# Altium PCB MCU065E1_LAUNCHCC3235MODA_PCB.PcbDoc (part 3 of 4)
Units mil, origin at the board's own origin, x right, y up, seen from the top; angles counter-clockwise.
Board outline 2300 x 4280 mil, 4 copper layers (TOP, GND, PWR, BOTTOM), stack 62 mil thick; 300 components, 199 nets, 970 pads, 475 vias.
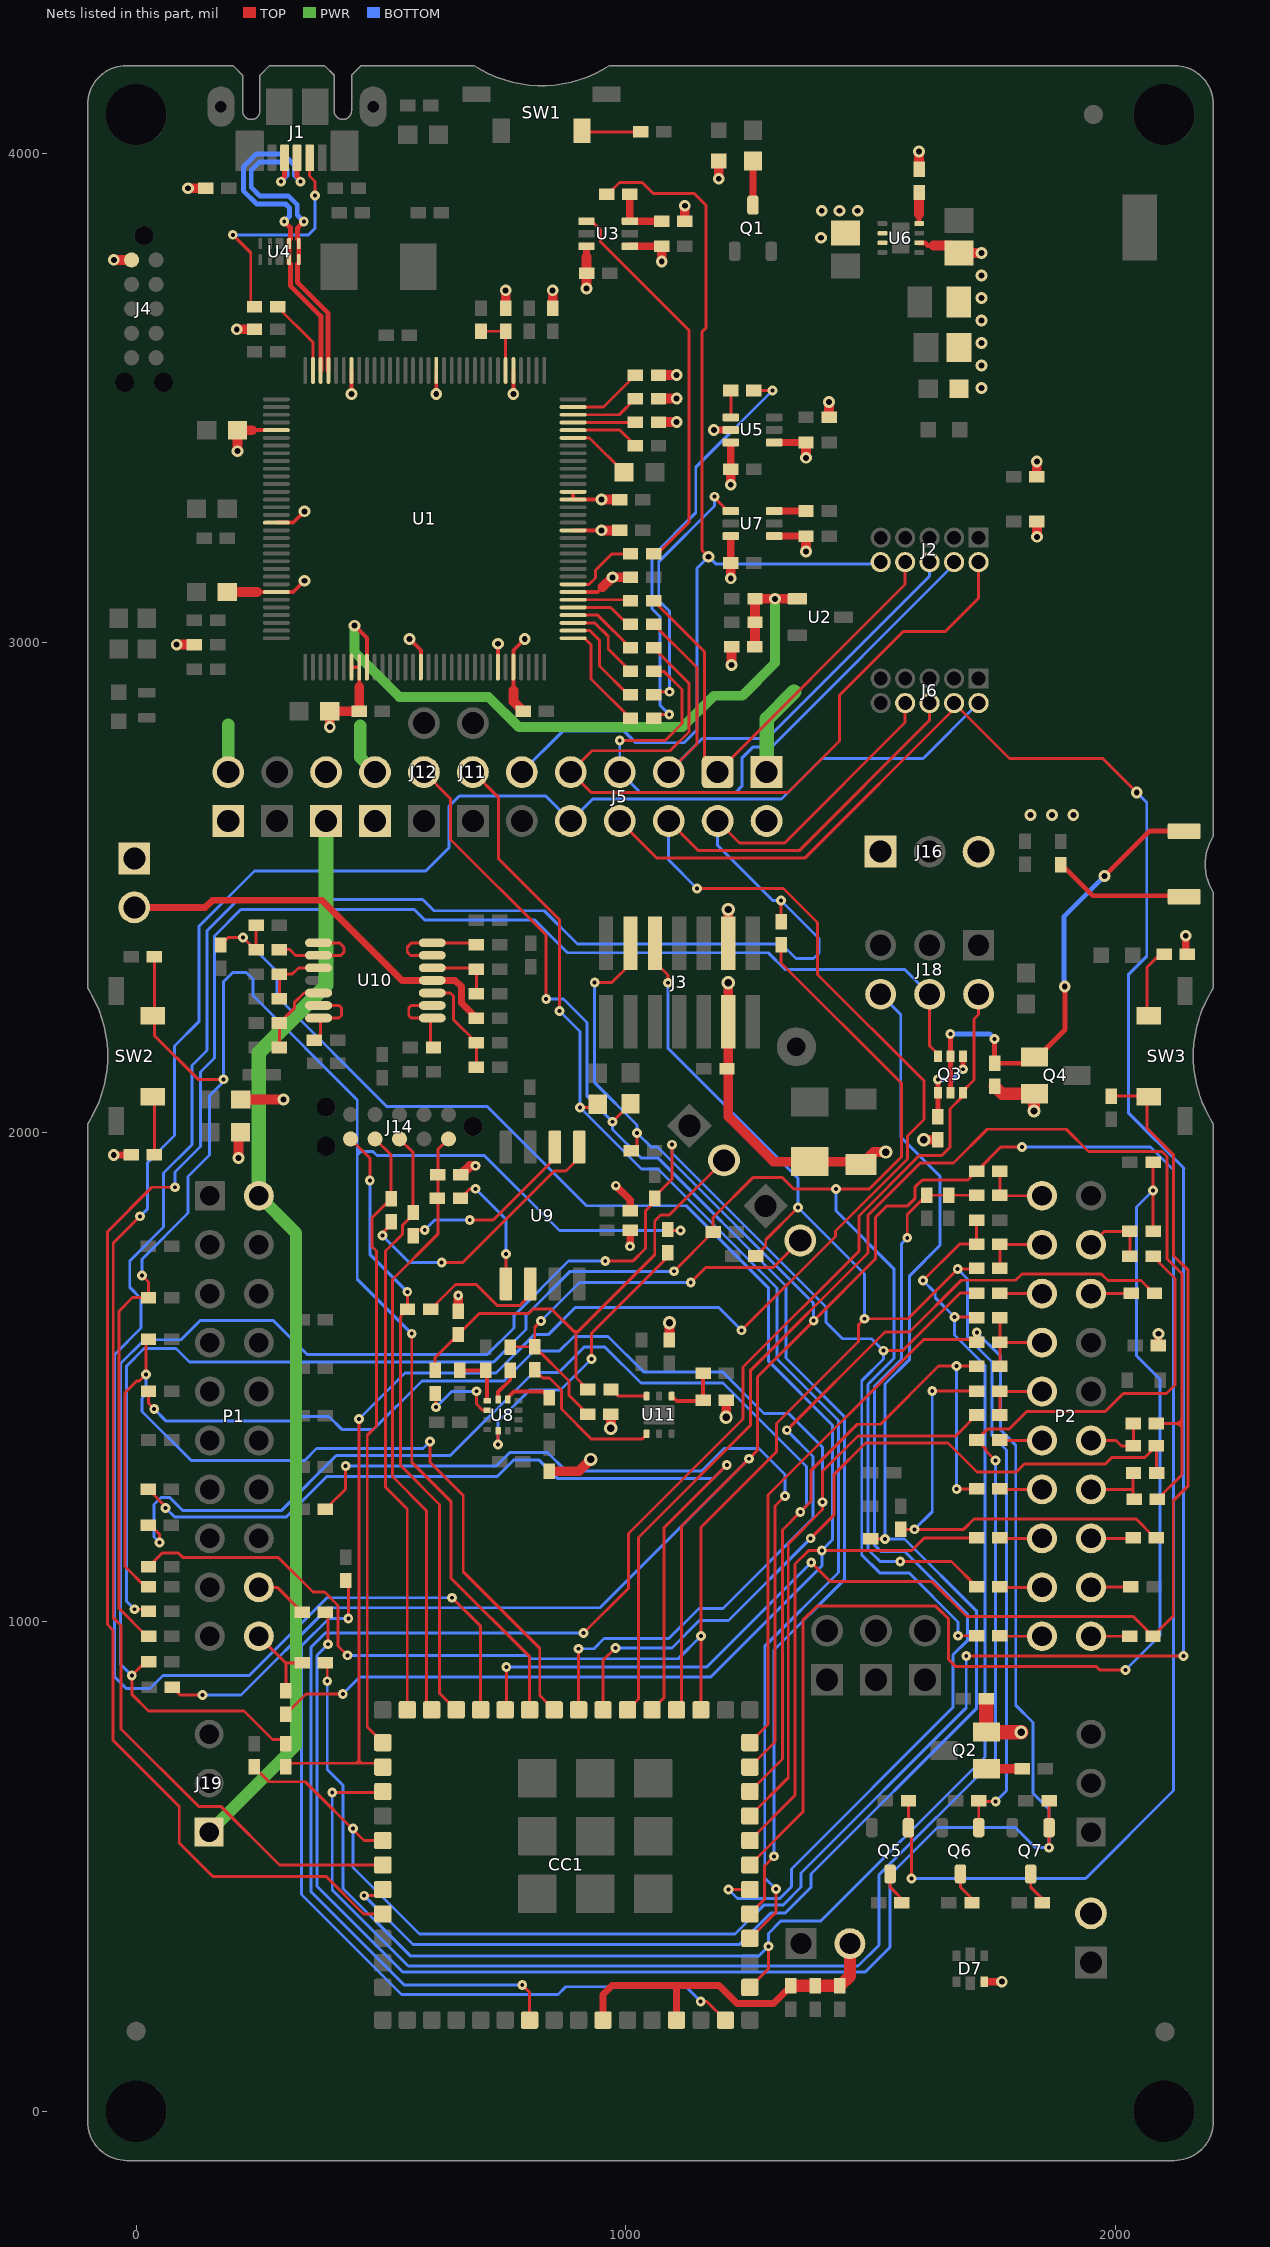
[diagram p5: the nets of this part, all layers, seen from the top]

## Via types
v1: diameter 20, hole 8, TOP to BOTTOM, tented both sides, 270 vias
v2: diameter 24, hole 12, TOP to BOTTOM, tented both sides, 142 vias
v3: diameter 19.68, hole 7.87, TOP to BOTTOM, 36 vias
v4: diameter 27, hole 15, TOP to BOTTOM, tented both sides, 23 vias
v5: diameter 19.68, hole 7.87, TOP to BOTTOM, tented bottom, 4 vias

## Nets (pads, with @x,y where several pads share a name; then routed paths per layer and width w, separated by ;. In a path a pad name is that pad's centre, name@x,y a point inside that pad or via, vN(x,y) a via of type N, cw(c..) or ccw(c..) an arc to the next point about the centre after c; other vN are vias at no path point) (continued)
NetP1_29: P1.29 R87.1 | length 109.9
  TOP w6: P1.29@250.7,1070.26 288.12,1070.26 R87.1@339.38,1019
NetP1_30: P1.30 R91.1 R94.1 | length 169
  TOP w6: P1.30@250.7,970.26 304.96,916 ; R94.1@306,858.62 306,914.96 304.96,916 ; R91.1@339.38,916 304.96,916
NetP2_11: P2.11 R93.1 | length 79.5
  TOP w6: P2.11@1950.7,970.26 R93.1@2030.16,970.26
NetP2_12: P2.12 R89.1 | length 81.9
  TOP w6: P2.12@1950.7,1070.26 1951.7,1071.27 R89.1@2032.16,1071.27
NetP2_13: P2.13 R85.1 | length 86.9
  TOP w6: P2.13@1950.7,1170.26 2036.16,1170.26 R85.1@2037.16,1171.27
NetP2_14: P2.14 R81.1 R99.1 | length 140.7
  TOP w6: P2.14@1950.7,1270.26 2036.16,1270.26 ; R99.1@2037.58,1303.88 2036.16,1302.46 2036.16,1270.26 ; R81.1@2039.18,1250.48 2036.16,1253.5 2036.16,1270.26
NetP2_15: P2.15 R77.1 R96.1 | length 137
  TOP w6: P2.15@1950.7,1370.26 2001.82,1370.26 2013,1359.09 R77.1@2037.16,1359.09 R96.1@2037.16,1404.97
NetP2_18: P2.18 R67.1 | length 83
  TOP w6: P2.18@1950.7,1670.26 2032.24,1670.26 R67.1@2033.24,1671.27
NetP2_19: P2.19 R59.1 R63.1 | length 142
  TOP w6: P2.19@1950.7,1770.26 1977.85,1797.42 R59.1@2030.31,1797.42 R63.1@2030.27,1746.34
NetP2_31: P2.31 R92.2 | length 86.7
  TOP w6: R92.2@1764.41,971.27 1765.41,970.26 P2.31@1850.7,970.26
NetP2_32: P2.32 R88.2 | length 86.7
  TOP w6: R88.2@1764.41,1071.27 1765.41,1070.26 P2.32@1850.7,1070.26
NetP2_33: P2.33 R84.2 | length 86.7
  TOP w6: R84.2@1764.41,1171.27 1765.41,1170.26 P2.33@1850.7,1170.26
NetP2_34: P2.34 R80.2 | length 86.7
  TOP w6: R80.2@1764.41,1271.27 1765.41,1270.26 P2.34@1850.7,1270.26
NetP2_35: P2.35 R76.2 | length 86.7
  TOP w6: R76.2@1764.41,1371.27 1765.41,1370.26 P2.35@1850.7,1370.26
NetP2_36: P2.36 R73.2 R101.2 | length 135.7
  TOP w6: R101.2@1764.41,1422.27 R73.2@1764.41,1471.27 1765.41,1470.26 P2.36@1850.7,1470.26
NetP2_37: P2.37 R70.2 R95.2 R98.2 | length 185.7
  TOP w6: R98.2@1764.41,1522.27 R70.2@1764.41,1571.27 ; R95.2@1764.41,1621.27 R70.2@1764.41,1571.27 ; P2.37@1850.7,1570.26 1765.41,1570.26 R70.2@1764.41,1571.27
NetP2_38: P2.38 R66.2 | length 86.7
  TOP w6: R66.2@1764.41,1671.27 1765.41,1670.26 P2.38@1850.7,1670.26
NetP2_39: P2.39 R54.2 R62.2 | length 135.7
  TOP w6: R62.2@1764.41,1722.27 R54.2@1764.41,1771.27 1765.41,1770.26 P2.39@1850.7,1770.26
NetP2_40: P2.40 R53.2 R60.2 | length 135.7
  TOP w6: R60.2@1764.41,1920.27 R53.2@1764.41,1871.27 1765.41,1870.26 P2.40@1850.7,1870.26
NetQ1_3: Q1.3 R30.1 | length 90
  TOP w15: Q1.3@1260.14,3894.26 R30.1@1260.14,3984.26
NetQ2_1: Q2.1 R105.1 | length 73.4
  TOP w20: Q2.1@1736.83,699.71 R105.1@1810.21,699.71
NetQ3_1: Q3.1 Q3.4 R143.1 | length 162.4
  TOP w10: R143.1@1637.78,2031.92 Q3.1@1637.78,2080.72 v1(1637.78,2107.53) ; v1(1688.97,2128.71) Q3.4@1688.97,2155.52
  BOTTOM w10: v1(1637.78,2107.53) 1667.78,2107.53 v1(1688.97,2128.71)
NetQ3_2: Q3.2 Q3.5 Q4.1 R144.1 SW4.2 | length 988.6
  TOP w10: Q3.2@1663.37,2080.72 Q3.5@1663.37,2155.52 v1(1663.37,2201) ; v1(1753.78,2190.74) R144.1@1753.78,2140.89 1822.69,2140.89 Q4.1@1835.31,2153.5 1841.5,2153.5 1897.58,2209.58 v2@1897.58,2297.5 ; v2(1978.23,2523.25) 2070.57,2615.59 SW4.2@2110.5,2615.59 ; SW4.2@2110.5,2615.61 2116.65,2621.76 SW4.2@2141,2621.76
  BOTTOM w10: v1(1663.37,2201) 1743.52,2201 v1(1753.78,2190.74) ; v2@1895.45,2297.5 1895.45,2440.47 v2(1978.23,2523.25)
  other v2: 1897.22,2297.5
NetQ5_3: Q5.3 R145.1 | length 71.6
  TOP w6: Q5.3@1540.43,484.73 1540.43,457.72 R145.1@1571.93,426.22
NetQ6_3: Q6.3 R146.1 | length 71.6
  TOP w6: Q6.3@1684.05,484.73 1684.05,457.72 R146.1@1715.55,426.22
NetQ7_3: Q7.3 R147.1 | length 71.6
  TOP w6: Q7.3@1827.68,484.73 1827.68,457.72 R147.1@1859.17,426.22
NetR2_2: R2.2 U1.33 | length 225.8
  TOP w6: U1.33@892.71,3009.15 916.17,3009.15 929.43,2995.89 929.43,2926.16 R2.2@1009.95,2845.64
NetR3_1: R3.1 U1.95 | length 159.7
  TOP w6: R3.1@289.02,3686.18 361.21,3613.99 U1.95@361.21,3556.4
NetR4_2: R4.2 U1.34 | length 197.8
  TOP w6: U1.34@892.71,3024.9 926.83,3024.9 946.38,3005.35 946.38,2952.44 R4.2@1005.18,2893.64
NetR6_2: R6.2 U1.35 | length 173.6
  TOP w6: U1.35@892.71,3040.65 937.12,3040.65 964.52,3013.25 964.52,2987.07 R6.2@1009.95,2941.64
NetR7_2: R7.2 U1.36 | length 144.9
  TOP w6: U1.36@892.71,3056.4 943.19,3056.4 R7.2@1009.95,2989.64
NetR8_2: R8.2 U1.37 | length 131.5
  TOP w6: U1.37@892.71,3072.15 969.51,3072.15 1004.01,3037.64 R8.2@1009.95,3037.64
NetR9_2: R9.2 U1.38 | length 118.2
  TOP w6: U1.38@892.71,3087.89 1007.7,3087.89 R9.2@1009.95,3085.64
NetR10_2: R10.2 U1.40 | length 152.1
  TOP w6: U1.40@892.71,3119.39 925.26,3119.39 938.31,3132.44 938.31,3147.98 971.97,3181.64 R10.2@1009.95,3181.64
NetR16_1: R16.1 U1.63 | length 154.3
  TOP w6: U1.63@892.71,3481.59 954.65,3481.59 R16.1@1019.95,3546.89
NetR17_1: R17.1 U1.62 | length 140.9
  TOP w6: U1.62@892.71,3465.85 986.9,3465.85 R17.1@1019.95,3498.89
NetR18_1: R18.1 U1.61 | length 127.6
  TOP w6: U1.61@892.71,3450.1 1019.16,3450.1 R18.1@1019.95,3450.89
NetR20_1: R20.1 U1.60 | length 140.3
  TOP w6: U1.60@892.71,3434.35 988.49,3434.35 R20.1@1019.95,3402.89
NetR24_1: R24.1 R25.2 U1.70 | length 130.4
  TOP w6: R25.2@704.56,3636.4 R24.1@754.91,3636.4 U1.70@754.91,3556.4
NetR27_2: R27.2 U1.59 | length 133.2
  TOP w6: U1.59@892.71,3418.6 926.46,3418.6 R27.2@996.81,3348.25
NetR28_1: R28.1 R29.2 U3.3 | length 120
  TOP w15: R29.2@1008.76,3916.37 U3.3@1008.76,3861.37 R28.1@1073.76,3861.37
NetR32_2: R32.2 SW1.1 | length 120
  TOP w6: SW1.1@910.98,4043.62 R32.2@1030.98,4043.62
NetR34_1: R34.1 U5.4 | length 55
  TOP w6: U5.4@1214.86,3460.37 R34.1@1214.86,3515.37
NetR36_1: R36.1 U6.8 | length 63.4
  TOP w10: U6.8@1599.51,3856.45 1599.51,3875.64
  TOP w20: 1599.51,3875.64 R36.1@1599.51,3919.88
NetR37_2: R37.2 U7.3 | length 65
  TOP w15: U7.3@1303.45,3269.19 R37.2@1368.45,3269.19
NetR40_2: R40.2 U9.1 | length 258.7
  TOP w6: R40.2@662.65,1865.18 681.85,1884.38 v1(693.3,1884.38) ; U9.1@755.4,1690.11 v1(755.6,1751.48)
  BOTTOM w6: v1(693.3,1884.38) 755.6,1822.08 v1(755.6,1751.48)
NetR41_2: R41.2 U9.6 | length 377.8
  TOP w6: R41.2@565.94,1788.8 577.3,1800.16 v1(589.59,1800.16) ; v1(681.5,1820.68) 729.45,1820.68 855.4,1946.62 U9.6@855.4,1969.64
  BOTTOM w6: v1(589.59,1800.16) 610.11,1820.68 v1(681.5,1820.68)
NetR42_2: R42.2 U9.5 | length 571.2
  TOP w6: v1(503,1788.78) 503,1793.48 521.02,1811.5 R42.2@521.02,1817.18 ; v1(624.2,1733.88) 667.41,1733.88 854.39,1920.86 878.04,1920.86 905.4,1948.23 U9.5@905.4,1969.64
  BOTTOM w6: v1(503,1788.78) 557.9,1733.88 v1(624.2,1733.88)
NetR43_2: R43.2 U9.2 | length 274
  TOP w6: R43.2@601.62,1638 652.38,1688.76 694.86,1688.76 737.98,1645.65 782.97,1645.65 805.4,1668.08 U9.2@805.4,1690.11
NetR108_2: R108.2 R112.2 U10.10 | length 135.5
  TOP w6: R112.2@292.48,2273.14 R108.2@292.48,2323.14 318.86,2323.14 331.45,2335.73 U10.10@372.72,2335.73
NetR109_1: R109.1 U10.8 U10.9 | length 201
  TOP w6: R109.1@292.48,2373.14 313.86,2373.14 325.68,2361.32 U10.9@372.72,2361.32 418.04,2361.32 424.37,2367.65 424.37,2377.75 415.21,2386.91 U10.8@376.65,2386.91
NetR110_2: R110.2 R113.2 U10.5 | length 141.3
  TOP w6: U10.5@605,2335.73 692.64,2335.73 R110.2@695.24,2333.14 R113.2@695.24,2283.14
NetR111_1: R111.1 U10.6 U10.7 | length 206.6
  TOP w6: U10.6@601.06,2361.32 560.68,2361.32 553.86,2368.14 553.86,2378.14 562.63,2386.91 U10.7@605,2386.91 691.46,2386.91 R111.1@695.24,2383.14
NetR116_2: R116.2 R122.2 U10.12 | length 162.2
  TOP w6: R122.2@292.48,2173.14 R116.2@292.48,2223.14 323.86,2254.52 323.86,2265.61 342.79,2284.55 U10.12@372.72,2284.55
NetR117_1: R117.1 U10.13 U10.14 | length 156.6
  TOP w6: R117.1@364.24,2187.84 376.65,2200.26 376.65,2233.37 414.59,2233.37 419.77,2238.55 419.77,2254.05 414.86,2258.96 U10.13@376.65,2258.96
NetR119_2: R119.2 R123.2 U10.3 | length 210.5
  TOP w6: U10.3@605,2284.55 642.08,2284.55 648.49,2278.14 648.49,2229.89 R119.2@695.24,2183.14 R123.2@695.24,2133.14
NetR120_1: R120.1 U10.1 U10.2 | length 170.7
  TOP w6: U10.2@601.06,2258.96 561.88,2258.96 556.97,2254.05 556.97,2238.65 562.25,2233.37 601.06,2233.37 601.06,2179.56 R120.1@607.48,2173.14
NetR128_1: R128.1 R132.2 U11.4 | length 124.7
  TOP w8: U11.4@1093.98,1460.99 1104.39,1450.58 1156.33,1450.58 R128.1@1158.39,1452.64 R132.2@1158.39,1507.79
NetR129_1: R129.1 R131.1 U8.1 | length 112.3
  TOP w8: R129.1@665.04,1513.56 R131.1@714.29,1513.56 714.29,1508.29 717.2,1505.37 U8.1@717.2,1451.71
NetR133_2: R133.2 U8.5 | length 599.8
  TOP w6: v1(739.44,1362.34) U8.5@739.44,1390.1 ; v1(930.3,1536.98) 930.3,1589.48 1085.9,1745.08 R133.2@1085.9,1754.05
  BOTTOM w6: v1(739.44,1362.34) 739.44,1408.92 804.1,1473.58 866.9,1473.58 v1(930.3,1536.98)
NetR135_1: R135.1 U11.6 | length 78.2
  TOP w6: R135.1@970.17,1474.4 983.58,1460.99 U11.6@1042.8,1460.99
NetR136_1: R136.1 U11.1 | length 315.7
  TOP w6: R136.1@814.29,1514.56 830.79,1498.06 844.32,1498.06 868.77,1473.61 868.77,1434.69 930.52,1372.94 1033.39,1372.94 1042.8,1382.35 U11.1@1042.8,1384.22
NetR138_1: R138.1 U8.2 | length 178.2
  TOP w6: R138.1@610.62,1466.32 612.72,1464.21 v1(612.72,1438.33) ; v1(695.2,1470.78) 695.2,1444.57 707.75,1432.03 U8.2@717.2,1432.03
  BOTTOM w6: v1(612.72,1438.33) 645.17,1470.78 v1(695.2,1470.78)
NetR140_1: R140.1 U8.11 | length 99.5
  TOP w8: U8.11@759.13,1454.27 759.13,1458.15 771.56,1470.58 831.52,1470.58 R140.1@844.29,1457.81
NetR141_1: R141.1 U8.12 | length 69.6
  TOP w8: U8.12@739.44,1454.27 739.44,1469.34 764.29,1494.19 R141.1@764.29,1513.56
NetR148_1: R148.1 SW2.2 | length 120
  TOP w6: R148.1@37.16,1953.6 SW2.2@37.16,2073.6
NetR149_1: R149.1 SW3.2 | length 144.1
  TOP w6: SW3.2@2065.14,2238.95 2065.14,2336.98 2092.19,2364.02 R149.1@2100.04,2364.02
NetR154_2: R154.2 SW4.1 | length 248.9
  TOP w10: R154.2@1888.8,2548.72 1954.46,2483.06 SW4.1@2110.5,2483.06
P01_GPIO_10: CC1.3 J3.9 Q6.1 R62.1 R86.1 R130.1 R151.2 | length 4809.4
  TOP w6: R86.1@25.16,1112.26 52.9,1140 86.79,1140 96.04,1130.75 291.1,1130.75 361.04,1060.81 385.1,1060.81 412.57,1033.34 412.57,950.38 v1(431.67,931.28) ; J3.9@1059.79,2380.75 1059.79,2348.15 1086.6,2321.34 v1(1086.6,2305.36) ; CC1.3@1153.9,819.92 v1(1153.9,970.88) 1153.9,1192.88 1308.3,1347.27 1308.3,1405.21 1475.51,1572.42 1475.51,1606.65 v1(1487.78,1618.92) 1576.81,1618.92 v1(1678.36,1720.47) 1715.37,1720.47 R62.1@1717.16,1722.27 ; R130.1@1265.72,1747.18 1286.26,1767.71 1286.26,1780.26 v1(1351.98,1845.98) ; Q6.1@1721.45,579.22 R151.2@1721.45,634.22 1723.22,632.45 v1(1755.95,632.45)
  BOTTOM w6: v1(431.67,931.28) 799.52,931.28 806.47,924.33 1107.36,924.33 v1(1153.9,970.88) ; v1(1086.6,2305.36) 1086.6,2171.48 1351.98,1906.1 v1(1351.98,1845.98) 1487.78,1710.18 v1(1487.78,1618.92) ; v1(1678.36,1720.47) 1698.45,1700.39 1698.45,1580.94 1748.59,1530.8 1748.59,1380.66 1778.25,1351 1778.25,654.75 v1(1755.95,632.45)
P02_GPIO_11: CC1.4 J3.11 Q5.1 R60.1 R90.1 R137.1 R150.2 | length 6349.6
  TOP w6: R90.1@73.62,866 89.62,850 v1(135.52,850) ; v1(936.8,2305.96) 971.78,2305.96 1009.79,2343.97 J3.11@1009.79,2380.75 ; R137.1@1011.68,1962.08 1023.43,1973.83 v1(1023.43,1998.46) ; CC1.4@1103.9,819.92 1114.36,830.38 1114.36,1195.41 v1(1251.82,1332.87) 1269.33,1350.38 1269.5,1350.38 1269.5,1500.38 v1(1384.2,1615.08) 1510.51,1741.39 1510.51,1826.24 1533.87,1849.6 1576.21,1849.6 1590.88,1864.27 1590.88,1887.43 1606.14,1902.7 1699.59,1902.7 R60.1@1717.16,1920.27 1766.51,1969.62 v1(1809.5,1969.62) ; R150.2@1577.83,634.22 Q5.1@1577.83,579.22 1584.04,573.01 v1(1584.04,475.59)
  BOTTOM w6: v1(135.52,850) 213.98,850 392.52,1028.54 947.49,1028.54 v1(1251.82,1332.87) ; v1(936.8,2305.96) 936.8,2101.28 1023.43,2014.65 v1(1023.43,1998.46) 1052.21,1969.68 1064.84,1969.68 1384.2,1650.31 v1(1384.2,1615.08) ; v1(1584.04,475.59) 1939.82,475.59 2119.17,654.94 2119.17,1922.83 2072.38,1969.62 v1(1809.5,1969.62)
P03_GPIO_12: CC1.9 R68.1 R102.1 | length 1929.6
  TOP w6: R102.1@25.16,1071.26 18.74,1071.26 -22.73,1112.73 -22.73,1467.58 1.76,1492.07 6.8,1492.07 v1(19.9,1505.18) 19.9,1572 R68.1@25.16,1577.26 ; v1(600.39,1367.93) 600.39,1325.81 668.22,1257.98 668.22,1102.05 824.57,945.7 824.57,849.25 CC1.9@853.9,819.92
  BOTTOM w6: v1(19.9,1505.18) 19.9,1463.68 12.1,1455.88 12.1,1429.68 111.98,1329.8 344.74,1329.8 368.71,1353.77 586.24,1353.77 v1(600.39,1367.93)
P04_GPIO_13: CC1.10 R64.1 R103.1 R133.1 R155.2 SW2.1 | length 4397.7
  TOP w6: v1(11.9,1707.17) 25.17,1693.91 R64.1@25.17,1662.26 -7.36,1662.26 -34.73,1634.89 -34.73,1026.98 22.21,970.04 R103.1@23.95,970.04 ; R155.2@37.16,2358.95 37.16,2238.95 37.16,2197.84 126.9,2108.09 v1(178.3,2108.09) ; v1(563.06,1588.41) 563.06,1325.77 643.66,1245.18 643.66,1088.55 803.9,928.31 CC1.10@803.9,819.92 ; R133.1@1085.9,1801.3 1089.02,1798.18 1089.89,1799.04 v1(1111.92,1799.04)
  BOTTOM w6: v1(11.9,1707.17) 11.9,1740.68 106,1834.77 106,1909.63 149.97,1953.6 149.97,2074.65 178.3,2102.98 v1(178.3,2108.09) 178.3,2307.51 197.59,2326.79 224.49,2326.79 238.47,2312.82 238.47,2279.21 451.76,2065.92 451.76,1968.28 ; v1(563.06,1588.41) 451.76,1699.72 451.76,1953.23 ; v1(1111.92,1799.04) 864.7,1799.04 711.36,1952.38 491.84,1952.38 483.46,1960.75 459.28,1960.75 ; 451.76,1953.23 459.28,1960.75 ; 451.76,1953.23 451.76,1960.75 ; 451.76,1960.75 451.76,1968.28 ; 451.76,1960.75 459.28,1960.75 ; 451.76,1968.28 459.28,1960.75
P05_GPIO_14: CC1.5 R78.1 | length 1846.4
  TOP w6: R78.1@25.16,1271.26 25.16,1269.98 60.2,1234.95 v1(60.2,1232.38) ; CC1.5@1053.9,819.92 1078.58,844.6 1078.58,1192.16 v1(1206.8,1320.38)
  BOTTOM w6: v1(60.2,1232.38) 78.78,1213.79 306.75,1213.79 389.96,1297 738.15,1297 771.19,1330.04 823.31,1330.04 860.43,1292.93 1179.35,1292.93 v1(1206.8,1320.38)
P06_GPIO_15: CC1.6 R81.2 R96.2 | length 2729.4
  TOP w6: CC1.6@1003.9,819.92 1026.1,842.12 1026.1,1172.03 1254.68,1400.61 1254.68,1512.88 1494.91,1753.11 1494.91,1830.36 1601.9,1937.35 1669.97,1937.35 1738.74,2006.12 1899.99,2006.12 1945.55,1960.56 2095.59,1960.56 2105.91,1950.23 2105.91,1741.38 2136.4,1710.89 2136.4,1413.3 ; R96.2@2084.41,1404.97 2128.07,1404.97 ; R81.2@2086.42,1250.48 2136.4,1300.45 2136.4,1396.64 ; 2128.07,1404.97 2136.4,1413.3 ; 2128.07,1404.97 2136.4,1404.97 ; 2128.07,1404.97 2136.4,1396.64 ; 2136.4,1396.64 2136.4,1404.97 ; 2136.4,1404.97 2136.4,1413.3
P07_GPIO_16: CC1.7 R77.2 R99.2 | length 1565
  TOP w6: CC1.7@953.9,820.94 953.9,921.21 v1(979.2,946.51) ; v1(1378,1170.38) 1425.32,1217.69 1425.32,1300.47 1489.85,1365 1658.88,1365 1717.98,1305.9 1798.11,1305.9 1814.5,1322.28 1979.98,1322.28 1993.48,1335.78 2061.1,1335.78 R77.2@2084.41,1359.09 2084.41,1304.29 R99.2@2084.82,1303.88
  BOTTOM w6: v1(979.2,946.51) 1094.59,946.51 1150.61,1002.53 1210.15,1002.53 v1(1378,1170.38)
P08_GPIO_17: CC1.8 R67.2 | length 1815
  TOP w6: CC1.8@903.9,820.94 v1(903.9,944.78) ; v1(1329.3,1391.28) 1529.86,1591.84 1580.06,1591.84 1685.87,1697.65 1796.64,1697.65 1809.53,1710.54 1971.91,1710.54 1985.37,1697.08 2052.86,1697.08 2076.99,1672.96 2078.8,1672.96 R67.2@2080.49,1671.27
  BOTTOM w6: v1(903.9,944.78) 935.19,944.78 955.92,965.51 1088.13,965.51 1149.86,1027.23 1198.66,1027.23 1382.93,1211.51 1382.93,1337.65 v1(1329.3,1391.28)
P15_GPIO_22: CC1.11 R93.2 R156.2 SW3.1 | length 2800.4
  TOP w6: CC1.11@753.9,820.94 756.25,823.29 v1(756.25,907.72) ; v1(1379.2,1121.08) 1417.75,1082.53 1625.51,1082.53 1697.28,1010.76 2036.91,1010.76 R93.2@2077.41,970.26 2118.8,1011.65 2118.8,1247.28 2149.31,1277.8 2149.31,1718.02 2118.91,1748.42 2118.91,1954.2 2065.14,2007.97 2065.14,2073.6 R156.2@1992.54,2073.6
  BOTTOM w6: v1(756.25,907.72) 1165.84,907.72 v1(1379.2,1121.08)
P16_GPIO_23: R46.1 R88.1 R97.1 R134.1 | length 3967.5
  TOP w6: v1(-3.51,1025.46) 20.96,1025.46 R97.1@25.16,1021.26 ; v1(1098.55,1716.04) 1178.78,1796.27 1178.78,1825.75 1260.95,1907.92 1319.73,1907.92 1343.59,1884.06 v1(1429.55,1884.06) 1497.7,1884.06 1563.91,1950.27 1563.91,2099.46 1317.6,2345.78 R46.1@1317.6,2382.85 ; v1(1561.03,1122.83) 1665.61,1122.83 R88.1@1717.16,1071.27
  BOTTOM w6: v1(-3.51,1025.46) -19.84,1041.79 -19.84,1522.09 16.3,1558.23 81.47,1558.23 109.26,1530.44 730.37,1530.44 796.66,1596.73 796.66,1625.87 886.67,1715.88 1098.38,1715.88 v1(1098.55,1716.04) ; v1(1429.55,1884.06) 1429.55,1839.6 1547.99,1721.16 1547.99,1537.68 1495.35,1485.04 1495.35,1147.5 1520.03,1122.83 v1(1561.03,1122.83)
P16_JTAG_TDI: CC1.12 J5.2 J6.8 R46.2 | length 4934.7
  TOP w6: v1(645.5,1048.98) 703.9,990.58 CC1.12@703.9,819.92 ; J5.2@1188,2635.86 1232.86,2591 1325,2591 1571,2837 J6.8@1571,2876.86 ; R46.2@1317.6,2430.1 v1(1317.6,2473.38)
  BOTTOM w6: v1(645.5,1048.98) 389.98,1048.98 231.25,890.24 54.75,890.24 28.05,863.54 -20.27,863.54 -43.84,887.1 -43.84,1546.16 10,1600 10,1660 -13.1,1683.1 -13.1,1737.08 56.11,1806.29 56.11,1916.49 114.13,1974.5 114.13,2136.13 144.97,2166.97 144.97,2411.63 208.73,2475.4 585.35,2475.4 608.23,2452.51 833.64,2452.51 901.58,2384.58 1318.33,2384.58 1348.23,2354.68 1383.94,2354.68 1395.1,2365.84 1395.1,2395.88 v1(1317.6,2473.38) 1300.45,2473.38 1188,2585.82 J5.2@1188,2635.86
P17_GPIO_24: R45.1 R66.1 R92.1 R100.1 R139.1 | length 4192.7
  TOP w6: R100.1@25.38,918 19.19,918 v1(-8.81,890) -8.81,851.81 25.19,817.81 220.55,817.81 278.74,759.61 297.01,759.61 R45.1@306,750.62 ; v1(958.3,1736.88) 1014.47,1736.64 1040.5,1762.68 1040.5,1839.41 1059.3,1858.21 R139.1@1059.3,1864.75 1059.3,1868.45 1094.67,1903.82 v1(1094.67,1974.59) ; v1(1526.99,1553.68) 1565.51,1553.68 1683.1,1671.27 R66.1@1717.16,1671.27 ; v1(1679.17,971.27) R92.1@1717.16,971.27
  BOTTOM w6: v1(-8.81,890) -31.84,913.03 -31.84,1527.44 16.81,1576.09 91.41,1576.09 130.33,1615 280.49,1615 349.18,1546.31 717.89,1546.31 771.69,1600.12 771.69,1625.24 883.33,1736.88 v1(958.3,1736.88) ; v1(1094.67,1974.59) 1094.67,1957.49 1409.38,1642.78 1409.38,1611.69 1442.96,1578.11 1502.56,1578.11 v1(1526.99,1553.68) 1526.99,1536.82 1482.46,1492.29 1482.46,1136.42 1519.03,1099.85 1578.83,1099.85 1679.17,999.51 v1(1679.17,971.27)
P17_JTAG_TDO: CC1.18 J5.4 J6.6 R45.2 | length 4030.9
  TOP w6: R45.2@306,703.38 313.51,710.89 449.66,710.89 ; v1(455.09,1414) 455.09,716.33 ; CC1.18@503.94,702.99 496.04,710.89 460.53,710.89 ; J5.4@1088,2635.86 1148.68,2575.18 1354.7,2575.18 1621,2841.48 J6.6@1621,2876.86 ; v1(1146.07,2498.12) 1322.55,2498.12 1392.23,2428.44 1392.23,2322.5 1609.41,2105.32 1609.41,2025.81 1576.12,1992.52 1576.12,1945.51 1428.65,1798.03 1428.65,1787.02 v1(1236.9,1595.28) ; 449.66,710.89 460.53,710.89 ; 449.66,710.89 455.09,716.33 ; 455.09,716.33 460.53,710.89
  BOTTOM w6: v1(455.09,1414) 549.26,1508.17 734.99,1508.17 813.3,1586.48 841.7,1586.48 897.08,1641.86 1190.32,1641.86 v1(1236.9,1595.28) ; J5.4@1088,2635.86 1088,2556.19 v1(1146.07,2498.12)
P18_GPIO_28: CC1.19 R63.2 R76.1 | length 3382.2
  TOP w6: v1(400.69,651.3) 502.25,651.3 CC1.19@503.94,652.99 ; v1(1755.4,1329.48) 1736.22,1348.66 1736.22,1352.21 R76.1@1717.16,1371.27 1739.98,1394.08 1784.3,1394.08 1820.04,1429.82 1980.54,1429.82 2016.76,1466.05 2105.08,1466.05 2122.54,1483.5 2122.54,1701.32 R63.2@2077.52,1746.34
  BOTTOM w6: v1(400.69,651.3) 400.69,451.71 555.97,296.43 1474.75,296.43 1517.5,339.19 1517.5,482.86 1755.4,720.76 v1(1755.4,1329.48)
P19_JTAG_TCK: CC1.21 J5.6 J6.4 R47.2 | length 5596.6
  TOP w6: R47.2@241,703.38 271.29,673.09 345.6,673.09 465.71,552.99 CC1.21@503.94,552.99 ; J5.6@988,2635.86 1063.22,2560.64 1367.05,2560.64 J6.4@1671,2864.59 ; J6.4@1671,2876.86 1784.42,2763.44 1974.76,2763.44 v2(2044.2,2694) ; v1(1695.9,930.06) v1(2139.85,930.06)
  BOTTOM w6: v1(443.08,577.64) 443.08,497.96 579.06,361.98 1223.19,361.98 1282.16,420.94 1321.43,420.94 1358.47,457.98 1358.47,486.59 1695.9,824.01 v1(1695.9,930.06) ; v2(2044.2,2694) 2064.7,2673.5 2064.7,2359.5 2027,2321.8 2027,2039.81 2140.59,1926.23 2139.85,1925.49 v1(2139.85,930.06)
P20_JTAG_TMS: CC1.22 J5.8 J6.2 | length 4242.2
  TOP w6: v1(7.83,1828.16) -46.73,1773.6 -46.73,1007.98 -31.01,992.26 -31.01,781.06 127.2,622.85 172.83,622.85 292.69,502.99 CC1.22@503.94,502.99
  BOTTOM w6: v1(7.83,1828.16) 23.56,1843.9 23.56,1938.34 78.54,1993.31 78.54,2175.97 128.12,2225.55 128.12,2420.1 241.71,2533.69 591.51,2533.69 639.06,2581.24 639.06,2665.92 660.22,2687.08 836.79,2687.08 J5.8@888,2635.86 932.76,2680.62 1318.21,2680.62 1401.36,2763.76 1607.9,2763.76 J6.2@1721,2876.86
P21_GPIO_25: R51.2 R73.1 R85.2 | length 935.5
  TOP w6: R51.2@1561.65,1188.79 v1(1590.45,1188.79) 1690.63,1188.79 1711.61,1209.77 2043.23,1209.77 2081.73,1171.27 R85.2@2084.41,1171.27 ; v1(1626.4,1471.27) R73.1@1717.16,1471.27
  BOTTOM w6: v1(1590.45,1188.79) 1626.4,1224.75 v1(1626.4,1471.27)
P50_GPIO_00: CC1.44 R54.1 R55.1 R91.2 R95.1 | length 3388.2
  TOP w6: R91.2@386.62,916 390.42,912.2 v1(390.42,878.54) ; CC1.44@1253.86,252.99 1291.7,290.83 v1(1291.7,336.88) ; v1(1607.77,1696.93) 1682.11,1771.27 R54.1@1717.16,1771.27 R55.1@1717.16,1820.27 ; v1(1671.7,1622.78) 1715.65,1622.78 R95.1@1717.16,1621.27
  BOTTOM w6: v1(390.42,878.54) 390.42,698.14 422.5,666.06 422.5,454.96 560.03,317.43 1272.26,317.43 v1(1291.7,336.88) 1291.7,363.11 1317.54,388.95 1399,388.95 1733.93,723.88 1733.93,1523.3 1671.7,1585.53 v1(1671.7,1622.78) 1632.52,1661.96 1632.52,1672.17 v1(1607.77,1696.93)
P53_GPIO_30: CC1.42 R83.2 | length 1692
  TOP w6: R83.2@428,1084.13 433.51,1078.62 v1(433.51,1006.81) ; v1(1153.3,224.08) 1165.88,224.08 CC1.42@1203.9,186.06
  BOTTOM w6: v1(433.51,1006.81) 393.73,1006.81 337.83,950.91 337.83,442.78 542.15,238.46 861.84,238.46 877.57,254.19 1123.19,254.19 v1(1153.3,224.08)
P55_GPIO_01: CC1.46 J11.2 R22.1 | length 2843
  TOP w6: J11.2@688,2735.86 740.59,2683.27 740.59,2558.48 864.91,2434.15 v1(864.91,2247.93) ; v1(906.9,2050.76) 936.1,2050.76 R22.1@942.79,2057.45 ; CC1.46@1254.88,354.01 1307.19,406.32 v1(1307.19,453.68)
  BOTTOM w6: v1(864.91,2247.93) 906.9,2205.95 v1(906.9,2050.76) 1032.61,1925.05 1066.05,1925.05 1309.4,1681.7 1309.4,1536.53 1434.75,1411.17 1434.75,1100.4 1284.18,949.82 1284.18,476.69 v1(1307.19,453.68)
P57_GPIO_02: CC1.47 J12.2 R21.1 | length 2861.4
  TOP w6: J12.2@588,2735.86 642.35,2681.51 642.35,2598.04 837.65,2402.73 v1(837.65,2272.37) ; v1(973.4,2021.36) 1009.79,2057.75 R21.1@1009.79,2058.45 ; CC1.47@1253.86,402.99 1283.68,432.81 1283.68,501.15 v1(1303.18,520.65)
  BOTTOM w6: v1(837.65,2272.37) 872.92,2272.37 921.3,2224 921.3,2073.47 v1(973.4,2021.36) 973.4,2005.78 1031.42,1947.76 1065.7,1947.76 1327.37,1686.09 1327.37,1538.7 1446.75,1419.31 1446.75,1085.56 1303.18,941.98 v1(1303.18,520.65)
P58_GPIO_03: CC1.48 R53.1 R56.1 R121.2 | length 2004.5
  TOP w6: v1(1210.41,452.99) CC1.48@1253.86,452.99 ; v1(1575.3,1784.28) 1575.3,1831.72 1614.85,1871.27 R56.1@1615,1871.27 R121.2@1660,1871.27 R53.1@1717.16,1871.27
  BOTTOM w6: v1(1210.41,452.99) 1228.73,434.68 1315.06,434.68 1339,458.62 1339,494.98 1669.05,825.03 1669.05,932.35 1698.75,962.04 1698.75,1014.81 1569.73,1143.83 1521.2,1143.83 1508.84,1156.19 1508.84,1481.55 1564,1536.72 1564,1772.98 v1(1575.3,1784.28)
P59_GPIO_04: CC1.49 R59.2 R118.2 | length 2501.5
  TOP w6: CC1.49@1253.86,502.99 1362.08,611.21 1362.08,1002.85 1390.96,1031.73 1633.66,1031.73 1659.51,1005.89 1659.51,923.11 1674.44,908.17 1961.87,908.17 1968.45,901.6 v1(2021.17,901.6) ; R59.2@2077.55,1797.42 v1(2077.55,1881.19) ; v1(2077.55,1881.19) R118.2@2077.59,1938.27
  BOTTOM w6: v1(2021.17,901.6) 2091.66,972.09 2091.66,1495.47 2043.87,1543.25 2043.87,1847.47 v1(2077.55,1881.19)
P60_GPIO_05: C36.1 CC1.50 R84.1 R94.2 R107.2 R109.2 | length 4389.2
  TOP w6: R107.2@173.06,2382.61 188.11,2397.65 v1(218.47,2397.65) 245.24,2370.89 R109.2@245.24,2373.14 C36.1@245.24,2423.14 ; R94.2@306,811.38 347.09,852.46 v1(422.28,852.46) ; CC1.50@1253.86,552.99 1346.23,645.36 1346.23,1117.81 1374.04,1145.62 v1(1400.84,1145.62) 1584.44,1145.62 1610.09,1171.27 R84.1@1717.16,1171.27
  BOTTOM w6: v1(218.47,2397.65) 287.59,2328.53 287.59,2277.18 511.96,2052.81 717.24,2052.81 920.29,1849.76 1123.95,1849.76 1292.25,1681.46 1292.25,1531.96 1422.75,1401.46 1422.75,1167.53 v1(1400.84,1145.62) 1400.84,1113.99 1173.58,886.73 456.55,886.73 v1(422.28,852.46)
P61_GPIO_06: CC1.51 R71.1 R101.1 | length 2846.1
  TOP w6: R71.1@25.16,1471.26 25.16,1446.31 v1(36.8,1434.68) ; CC1.51@1253.86,602.99 1332.25,681.38 1332.25,1158.99 1402.3,1229.04 v1(1402.3,1244.28) 1402.3,1307.2 1474.76,1379.66 1674.57,1379.66 R101.1@1717.97,1423.06
  BOTTOM w6: v1(36.8,1434.68) 61.7,1409.77 321.72,1409.77 331.19,1419.24 394,1419.24 420.24,1393 485,1393 583.78,1491.78 751.57,1491.78 812.87,1553.08 864.6,1553.08 894.47,1582.95 964.02,1582.95 1036.46,1510.51 1197.9,1510.51 1282.78,1425.62 1333.16,1425.62 1402.3,1356.49 v1(1402.3,1244.28)
P62_GPIO_07: CC1.52 R80.1 R82.1 R98.1 | length 3244.7
  TOP w6: R82.1@24.38,1197 29,1197 47.5,1178.5 v1(47.5,1161.58) ; CC1.52@1253.86,652.99 1320.25,719.38 1320.25,1187.53 v1(1356.9,1224.18) 1379.07,1246.34 1379.07,1309.44 1473.05,1403.42 1520.63,1403.42 1639.47,1522.26 v1(1675.8,1522.26) R98.1@1717.16,1522.27 ; v1(1676.39,1271.27) R80.1@1717.16,1271.27
  BOTTOM w6: v1(47.5,1161.58) 36.19,1172.88 36.19,1239.36 50.66,1253.82 68.83,1253.82 95.87,1226.78 296.27,1226.78 408.88,1339.39 641.72,1339.39 811.64,1509.31 863.27,1509.31 914.8,1560.85 958,1560.85 1031.19,1487.65 1198.94,1487.65 1369.49,1317.1 1369.49,1236.77 v1(1356.9,1224.18) ; v1(1675.8,1522.26) 1676.39,1521.67 v1(1676.39,1271.27)
P63_GPIO_08: CC1.53 R79.2 | length 1698.9
  TOP w6: R79.2@386.62,1230 428,1271.38 v1(428,1318) ; CC1.53@1253.86,702.99 1305.14,754.27 1305.14,1236.47 v1(1325.76,1257.09)
  BOTTOM w6: v1(428,1318) 735.48,1318 763.31,1345.83 840.56,1345.83 878.76,1307.62 1154.92,1307.62 1201.17,1353.87 1272.56,1353.87 1325.76,1300.67 v1(1325.76,1257.09)
P64_GPIO_09: CC1.54 Q7.1 R70.1 R87.2 R152.2 | length 4679.5
  TOP w6: R87.2@386.62,1019 393.57,1012.05 392.07,1010.55 v1(392.07,953.98) ; CC1.54@1253.86,752.99 1291.1,790.23 1291.1,1259.05 1608.33,1576.28 R70.1@1717.16,1576.28 ; R70.1@1717.16,1571.27 R70.1@1717.16,1576.28 ; v1(1717.45,1591.1) 1717.16,1590.82 R70.1@1717.16,1576.28 ; R70.1@1722.18,1576.28 R70.1@1717.16,1576.28 ; v1(1865.08,538.38) Q7.1@1865.08,579.22 R152.2@1865.08,634.22
  BOTTOM w6: v1(392.07,953.98) 369.46,931.37 369.46,459.73 544.76,284.43 1489.52,284.43 1540.15,335.06 1540.15,482.44 1637.11,579.4 1796.11,579.4 1837.14,538.38 v1(1865.08,538.38) 1865.08,616.63 1832.35,649.35 1832.35,793.88 1797,829.23 1797,1360.72 1766.23,1391.49 1766.23,1542.32 v1(1717.45,1591.1)
SENS_I2C_SCL: J23.2 R126.1 R136.2 R141.2 | length 888.7
  TOP w6: R141.2@764.29,1560.81 765.29,1561.81 R136.2@814.29,1561.81 ; v1(827,1614.48) 814.29,1601.76 R136.2@814.29,1561.81 ; R126.1@922.67,1424.19 884.3,1462.55 884.3,1491.8 R136.2@814.29,1561.81 ; v1(1133,1693.28) 1162.95,1723.23 1301.16,1723.23 J23.2@1356.76,1778.82
  BOTTOM w6: v1(827,1614.48) 905.8,1693.28 v1(1133,1693.28)
SENS_I2C_SDA: J24.2 R127.1 R135.2 R138.2 | length 996.6
  TOP w6: R138.2@610.62,1513.56 610.62,1539.41 R127.1@658.02,1586.81 700.98,1629.78 802.07,1629.78 810.87,1638.58 848.8,1638.58 894.85,1592.52 ; R135.2@922.92,1474.4 898.5,1498.82 898.5,1588.88 ; J24.2@1200.96,1942.52 1089.31,1830.88 1071.5,1830.88 1059.5,1818.88 1059.5,1749.88 902.15,1592.52 ; 894.85,1592.52 898.5,1588.88 ; 894.85,1592.52 902.15,1592.52 ; 898.5,1588.88 902.15,1592.52
SOP0: CC1.34 J18.2 Q3.3 | length 3323.7
  TOP w6: v1(788.75,257.91) 803.9,242.76 CC1.34@803.9,186.06 ; v1(913.99,976.72) 1005.66,1068.39 1005.66,1180.1 1239.88,1414.33 1239.88,1520.18 1476.52,1756.81 1476.52,1828.94 1599.8,1952.22 1645.62,1952.22 1662.7,1969.3 1662.7,2047.24 1688.97,2073.5 Q3.3@1688.97,2080.72 1688.97,2083.97 1711.47,2106.47 1711.47,2231.07 1721,2240.6 J18.2@1721,2281.86
  BOTTOM w6: v1(788.75,257.91) 548.49,257.91 548.04,257.46 356.85,448.65 356.85,947.31 386.25,976.72 v1(913.99,976.72)
SOP1: CC1.24 J18.4 Q3.6 | length 4196.5
  TOP w6: v1(79.3,1887.68) 32.08,1887.68 -58.73,1796.86 -58.73,994.22 -47.64,983.12 -47.64,758.07 88.02,622.42 88.02,547.91 156.69,479.24 388.33,479.24 464.57,402.99 CC1.24@503.94,402.99 ; J18.4@1621,2281.86 1621,2176.67 1636.93,2160.74 1636.93,2156.37 Q3.6@1637.78,2155.52
  BOTTOM w6: v1(79.3,1887.68) 79.3,1918.95 131.31,1970.96 131.31,2122.8 160,2151.48 160,2401.1 213.87,2454.97 568.38,2454.97 590.09,2433.26 814.61,2433.26 881.19,2366.68 1291.2,2366.68 1325.44,2332.43 1570.43,2332.43 J18.4@1621,2281.86
SOP2: CC1.23 D5.2 J18.6 | length 3237.1
  TOP w6: v1(465.9,440.28) 491.23,440.28 CC1.23@503.94,452.99 ; D5.2@1500.95,1169.11 v1(1529.84,1169.11)
  BOTTOM w6: v1(465.9,440.28) 565.56,340.62 1232.15,340.62 1296.03,404.51 1325.78,404.51 1378.68,457.41 1378.68,484.78 1717.24,823.33 1717.24,1021.48 1569.61,1169.11 v1(1529.84,1169.11) 1529.84,1485.58 1580.29,1536.03 1580.29,1706.87 1642.39,1768.97 1642.39,1909.96 1562.07,1990.28 1562.07,2240.79 J18.6@1521,2281.86
SPI_CLK: CC1.15 J14.8 R41.1 | length 1219.7
  TOP w6: J14.8@538.2,1986.38 565.94,1958.64 R41.1@565.94,1836.04 565.94,1831.86 544.22,1810.14 544.22,1791.8 509.58,1757.15 509.58,1274.52 553.9,1230.2 CC1.15@553.9,819.92
SPI_CS_IN: CC1.14 J14.10 R40.1 R44.2 | length 1247.2
  TOP w6: CC1.14@603.9,819.92 593.41,830.41 593.41,1226.62 523.54,1296.49 523.54,1698.92 616.3,1791.68 R44.2@616.3,1913.28 616.3,1964.48 J14.10@638.2,1986.38
SPI_MISO: CC1.13 J14.6 R43.1 | length 1267.7
  TOP w6: J14.6@438.2,1986.38 477.43,1947.14 v1(477.43,1901.39) ; v1(554,1674) 554,1638.38 R43.1@554.38,1638 540,1623.62 540,1319.59 619.94,1239.64 619.94,853.87 CC1.13@653.9,819.92
  BOTTOM w6: v1(477.43,1901.39) 477.43,1750.57 v1(554,1674)
SPI_MOSI: CC1.17 J14.7 R42.1 | length 1288.2
  TOP w6: J14.7@488.2,1986.38 521.02,1953.56 R42.1@521.02,1864.43 481.41,1824.82 481.41,1766.59 490.81,1757.19 490.81,1399.77 472.1,1381.06 472.1,784.83 CC1.17@503.94,752.99
VBAT_CC: C27.1 C28.1 C31.1 C32.1 C33.1 CC1.37 CC1.40 J3.3 J3.4 J10.1 J13.2 J16.1 Q2.2 R19.2 R39.2 R44.1 R57.1 R104.2 | length 1778
  TOP w14: CC1.37@953.9,186.06 953.9,238.49 972.38,256.98 1191.1,256.98 1228,220.08 1301.93,220.08 C32.1@1337.75,255.89 ; CC1.40@1103.9,186.06 1103.9,256.58
  TOP w15: v1(980,1890.78) 1009.12,1861.65 R39.2@1009.12,1839.98
  TOP w20: R57.1@213.58,2066.92 v2(301.17,2066.92) ; R44.1@663.55,1913.28 681.65,1931.38 v1(693.3,1931.38) ; v4(1209.79,2305.58) J3.4@1209.79,2225.83 1209.79,2032.37 1302.34,1939.82 C27.1@1376.59,1939.82 1474.68,1939.82 C28.1@1480.59,1933.92 1506.13,1959.46 v4(1531.6,1959.46) ; J3.3@1209.79,2386.07 v4(1209.79,2455.19)
  TOP w25: C32.1@1337.75,256.51 1438.37,256.51 1458.24,276.38 J13.2@1458.24,342.43
  TOP w30: Q2.2@1736.64,774.33 v4(1807.93,774.33) ; Q2.2@1736.83,774.52 R104.2@1736.83,838.71
VBUS_USB1: C26.1 J9.2 L1.2 R5.2 R11.2 U6.2 U6.3 | length 109.1
  TOP w20: v2(82.75,2996.17) R11.2@119.12,2996.17 ; v2(105.69,3928.5) L1.2@142.06,3928.5 ; v2(205.41,3640.38) R5.2@241.77,3640.38
  other v2: 1398.92,3827.34 1400.63,3882.57 1436.93,3882.57 1474.01,3882.57
VCC_BRD: D7.4 J7.1 J8.2 J16.3 J21.1 J25.2 Q4.2 R1.1 R38.2 R58.1 R124.1 R125.2 R126.2 R127.2 R128.2 R142.2 R143.2 R144.2 R148.2 R149.2 | length 630.6
  TOP w15: v2(-45.83,1953.6) R148.2@-10.08,1953.6 ; v1(1009.12,1766.98) R38.2@1009.12,1800.18 ; D7.4@1732.9,264.62 v2(1768.65,264.62) ; R142.2@2088.45,1564.25 v2(2088.45,1588.37) ; v2(2144.33,2401.42) 2144.33,2366.98 R149.2@2147.28,2364.02
  TOP w20: v2(208.89,1947.45) 208.89,1995.68 R58.1@213.36,2000.15 ; R127.2@658.02,1634.06 v1(658.02,1666.25) ; R124.1@844.29,1307.56 904.69,1307.56 v4(928.75,1331.62) ; v4(969.47,1395.44) 969.91,1395.88 R126.2@969.91,1424.19 ; R125.2@1089.39,1575.62 v4@1089.39,1610.24 ; v4@1205.64,1417.64 R128.2@1205.64,1452.64 ; v4(1609.29,1984.67) R143.2@1637.78,1984.67 ; v2(1840.34,3216.37) R1.1@1840.34,3247.73
  TOP w25: R144.2@1753.78,2093.64 1768.72,2078.7 Q4.2@1835.31,2078.7 1834.28,2077.67 v4(1834.28,2043.25)
  other v2: 1827.17,2648.3 1870.92,2648.3 1914.67,2648.3
  other v4: 1205.26,1417.64 1089.77,1610.62
VCC_BUFFER: C19.1 C23.1 C30.1 D3.2 J8.1 R28.2 R33.2 U3.1 U5.1 U5.5 U7.1 | length 610.2
  TOP w15: U3.1@1008.76,3810.19 C19.1@1073.76,3810.19 ; v2(1180.29,3434.78) U5.5@1214.86,3434.78 ; U7.1@1303.45,3218.01 C30.1@1368.45,3218.01 ; U5.1@1303.45,3409.19 C23.1@1368.45,3409.19
  TOP w20: v2(1073.76,3778.83) C19.1@1073.76,3810.19 ; R28.2@1121,3861.37 v2(1121,3892.73) ; v2(1190.14,3947.9) D3.2@1190.14,3984.26 ; v2(1368.45,3186.65) C30.1@1368.45,3218.01 ; v2(1368.45,3377.83) C23.1@1368.45,3409.19 ; R33.2@1415.69,3460.37 v2(1415.69,3491.73)
  PWR w30: J8.1@1288,2735.86 1288,2844.15 1343.96,2900.11
VCC_LDO_3V3: C5.1 C6.1 C7.1 C8.1 C9.1 C10.1 C14.1 C15.1 C20.1 C22.1 C24.1 C25.1 C29.1 J4.1 J7.2 J10.2 L3.2 R13.1 R16.2 R17.2 R18.2 R23.1 R24.2 R26.2 R35.1 R36.2 U1.7 U1.8 U1.16 U1.26 U1.28 U1.39 U1.47 U1.51 U1.52 U1.69 U1.79 U1.90 U1.101 U1.113 U1.122 U3.6 U5.6 U6.6 U7.6 | length 2240.2
  TOP w7.87: 236.47,3434.35 U1.101@286.41,3434.35 ; 247.4,3103.64 U1.122@286.41,3103.64 320.95,3103.64 v2(344.11,3126.81) ; U1.113@286.41,3245.37 320.95,3245.37 v2(344.11,3268.54) ; U1.7@439.95,2950.1 U1.8@455.57,2950.1 ; v2(439.95,3508.3) U1.90@439.95,3556.4 ; 455.7,2910.02 U1.8@455.7,2950.1 ; v2(558.52,3007.8) 581.68,2984.64 U1.16@581.68,2950.1 ; v2(613.18,3508.3) U1.79@613.18,3556.4 ; U1.26@739.16,2950.1 v2(739.16,2997.98) ; 770.66,2902.22 U1.28@770.66,2950.1 770.66,2984.64 v2(793.83,3007.8) ; v2(770.66,3508.3) U1.69@770.66,3556.4 ; U1.39@892.71,3103.64 942.95,3103.64 952.95,3113.64 ; U1.47@892.71,3229.63 v2(950.7,3229.63) ; U1.51@892.71,3292.62 v2(950.7,3292.62) ; U1.51@892.71,3292.74 U1.52@892.71,3308.37
  TOP w10: U6.6@1599.51,3817.08 1611.82,3817.08 1617.47,3811.44 1629.24,3811.44
  TOP w15: 920.18,3788.37 U3.6@920.18,3810.19 ; C29.1@1214.86,3163.01 U7.6@1214.86,3218.01 ; C22.1@1214.86,3354.19 U5.6@1214.86,3409.19
  TOP w20: v2(-45.57,3782.26) J4.1@-9.21,3782.26 ; C9.1@186.36,3103.64 247.4,3103.64 ; v2(207.23,3391.49) C8.1@207.23,3434.35 236.47,3434.35 ; v2(395.7,2827.75) C10.1@395.7,2860.1 C7.1@455.7,2860.1 455.7,2910.02 ; R24.2@754.91,3683.64 v2(754.91,3720) ; 770.66,2902.22 770.66,2880.1 C6.1@790.66,2860.1 ; R23.1@850.91,3683.64 v2(850.91,3720) ; v2(920.18,3723.83) C20.1@920.18,3755.19 920.18,3788.37 ; v2(950.7,3229.63) C14.1@987.71,3229.63 ; v2(950.7,3292.62) C15.1@987.71,3292.62 ; 952.95,3113.64 v2(972.95,3133.64) C5.1@1009.95,3133.64 ; R18.2@1067.19,3450.89 v2(1104.2,3450.89) ; R17.2@1067.19,3498.89 v2(1104.2,3498.89) ; R16.2@1067.19,3546.89 v2(1104.2,3546.89) ; v2(1214.86,3131.65) C29.1@1214.86,3163.01 ; v2(1214.86,3322.83) C22.1@1214.86,3354.19 ; v2(1216.23,2954.57) 1216.23,2991.95 R26.2@1216.49,2992.2 ; R36.2@1599.51,3967.13 v2(1599.51,4003.49) ; 1629.24,3811.44 1665.71,3811.44 L3.2@1680.99,3796.16 v2@1727.35,3796.16 ; R13.1@1840.09,3338.87 v2(1840.09,3370.24)
  PWR w25: J7.2@188,2735.86 188,2833.06 ; 457.99,2830.27 457.99,2765.87 J10.2@488,2735.86
  other v2: 1726.94,3520.36 1726.94,3566.32 1726.94,3612.29 1726.94,3658.26 1726.94,3704.22 1726.94,3750.19 1726.94,3796.16
VCC_MCU_5V: J9.1 J19.1 P1.21 | length 2227.4
  PWR w25: J19.1@149.2,570.26 326.59,747.65 326.59,1794.37 P1.21@250.7,1870.26
  PWR w30: P1.21@250.7,1870.26 250.7,2162.69 388,2299.99 J9.1@388,2635.86
VCC_OPAMP: C35.1 J21.2 U10.4 | length 824.4
  TOP w14: J21.2@-3.7,2459.28 141.09,2459.28 155.67,2473.85 379.47,2473.85 543.18,2310.14 U10.4@605,2310.14 651.86,2310.14 664.57,2297.43 664.57,2263.81 C35.1@695.24,2233.14
VREFA: C12.1 C13.1 R26.1 U1.9 U2.1 | length 1440.7
  TOP w7.87: v2(446.09,3034.93) 471.45,3009.58 U1.9@471.45,2950.1
  TOP w20: R26.1@1264.32,2992.78 C13.1@1264.32,3041.71 C12.1@1264.32,3089.71 v2(1305.17,3089.71) U2.1@1350.79,3089.72
  PWR w20: v2(446.09,3034.93) 446.09,2980.85 537.67,2889.27 720.09,2889.27 781.63,2827.73 1116.19,2827.73 1180.06,2891.6 1238.24,2891.6 1305.17,2958.54 v2(1305.17,3089.71)
XDS_CC_nRESET: J2.10 J5.9 R29.1 | length 2089.4
  TOP w6: R29.1@961.52,3916.37 963.45,3916.37 987.44,3940.36 1033.86,3940.36 1056.07,3918.15 1139.63,3918.15 1164.58,3893.2 1164.58,3643.76 1156.03,3635.21 1156.03,3189.23 v2(1169.45,3175.8)
  BOTTOM w6: J5.9@788,2735.86 871.49,2819.35 997.11,2819.35 1020.68,2795.78 1119.32,2795.78 1145.91,2822.37 1145.91,3152.25 v2(1169.45,3175.8) 1184,3161.25 J2.10@1517.39,3161.25
XDS_JTAG_TCK: J2.4 J5.5 R6.1 | length 1276.1
  TOP w6: v1(988,2800.35) 1080.92,2800.35 1115.4,2834.83 1115.4,2904.35 1078.1,2941.64 R6.1@1057.19,2941.64
  BOTTOM w6: v1(988,2800.35) J5.5@988,2735.86 1029.67,2694.19 1224.86,2694.19 1237.37,2706.7 1237.37,2764.1 1259.92,2786.65 1297.86,2786.65 J2.4@1671,3159.78
XDS_JTAG_TDI: J2.8 J5.1 R9.1 | length 991.6
  TOP w6: R9.1@1057.19,3085.64 1161.36,2981.48 1161.36,2762.51 J5.1@1188,2735.86 1571,3118.86 J2.8@1571,3164.86
XDS_JTAG_TDO: J2.6 J5.3 R8.1 | length 1089.8
  TOP w6: R8.1@1057.19,3037.64 1145.57,2949.27 1145.57,2793.43 J5.3@1088,2735.86
  BOTTOM w6: J5.3@1088,2735.86 1156.24,2804.1 1289.1,2804.1 1621,3136 J2.6@1621,3164.86
XDS_JTAG_TMS: J2.2 J5.7 R7.1 | length 1620.4
  TOP w6: R7.1@1057.19,2989.64 1129.4,2917.44 1129.4,2817.9 1090.84,2779.34 931.48,2779.34 J5.7@888,2735.86 929.67,2694.19 1331.79,2694.19 1436.93,2799.34 1436.93,2892.93 1567,3023 1653.11,3023 1721,3090.89 J2.2@1721,3164.86
XDS_NRESET: R10.1 U3.4 | length 807
  TOP w6: U3.4@920.18,3861.37 930.84,3861.37 948.99,3843.22 948.99,3819 1129.04,3638.95 1129.04,3245.42 1065.26,3181.64 R10.1@1057.19,3181.64
XDS_UART_RX: R2.1 R34.2 | length 851.8
  TOP w6: R2.1@1057.19,2845.64 1065.29,2853.73 v1(1089.2,2853.73) ; R34.2@1262.11,3515.37 v1(1300.18,3515.37)
  BOTTOM w6: v1(1089.2,2853.73) 1069.89,2873.05 1069.89,3053.43 1053.74,3069.58 1053.74,3176 1143.24,3265.5 1143.24,3358.43 v1(1300.18,3515.37)
XDS_UART_TX: R4.1 U7.4 | length 536.1
  TOP w6: R4.1@1057.19,2893.64 1063.34,2899.79 v1(1089.37,2899.79) ; v1(1181.67,3298.4) 1181.67,3296.22 1208.71,3269.19 U7.4@1214.86,3269.19
  BOTTOM w6: v1(1089.37,2899.79) 1089.37,3064.35 1067.63,3086.09 1067.63,3165.43 1181.67,3279.48 v1(1181.67,3298.4)
XDSET_ID: J1.4 R3.2 | length 487.8
  TOP w6: v1(197.49,3833.49) 234.12,3796.85 234.12,3693.83 R3.2@241.77,3686.18 ; J1.4@354.38,3990.66 354.38,3953.44 365.61,3942.2 v1(365.61,3913.63)
  BOTTOM w6: v1(197.49,3833.49) 352.36,3833.49 365.61,3846.73 v1(365.61,3913.63)
XDSET_N: J1.2 U1.93 U4.1 U4.10 | length 689.7
  TOP w10: v1(295.79,3942.03) 295.79,3945.34 303.2,3952.75 J1.2@303.2,3990.66 ; v1(342.62,3860.46) 329.94,3847.78 329.94,3824.79 332.28,3822.45 U4.1@332.28,3815.67 U4.10@332.28,3782.8 332.28,3776.02 329.94,3773.68 329.94,3735.87 392.33,3673.47 U1.93@392.33,3556.4
  BOTTOM w10: v1(295.79,3942.03) 307.79,3954.03 307.79,3968.38 293.6,3982.56 252.22,3982.56 235.1,3965.45 235.1,3930.39 253.03,3912.46 311.82,3912.46 329.19,3895.09 329.19,3873.9 v1(342.62,3860.46)
XDSET_P: J1.3 U1.94 U4.2 U4.9 | length 737.6
  TOP w10: v1(302.62,3860.46) 314.94,3848.15 314.94,3824.79 312.59,3822.45 U4.2@312.59,3815.67 U4.9@312.59,3782.8 312.59,3776.02 314.94,3773.68 314.94,3729.65 377.33,3667.26 U1.94@377.33,3556.4 ; J1.3@328.79,3990.66 328.79,3952.69 v1@335.79,3945.69
  BOTTOM w10: v1(302.62,3860.46) 313.19,3871.03 313.19,3888.46 305.19,3896.46 246.41,3896.46 219.1,3923.77 219.1,3972.07 245.59,3998.56 300.23,3998.56 323.79,3975.01 323.79,3954.03 v1(335.79,3942.03)
pads on no net: CC1.20 CC1.31 CC1.33 CC1.39 CC1.41 CC1.45 CC1.55@1034.41,658.5 CC1.55@1034.41,701.81 CC1.56@916.3,658.5 CC1.56@916.3,701.81 CC1.56@959.61,658.5 CC1.56@959.61,701.81 CC1.57@798.19,658.5 CC1.57@798.19,701.81 CC1.57@841.5,658.5 CC1.57@841.5,701.81 CC1.58@1034.41,540.39 CC1.58@1034.41,583.7 CC1.58@1077.72,540.39 CC1.58@1077.72,583.7 CC1.59@916.3,540.39 CC1.59@916.3,583.7 CC1.59@959.61,540.39 CC1.59@959.61,583.7 CC1.60@798.19,540.39 CC1.60@798.19,583.7 CC1.60@841.5,540.39 CC1.60@841.5,583.7 CC1.61@1034.41,422.28 CC1.61@1034.41,465.59 CC1.61@1077.72,422.28 CC1.61@1077.72,465.59 CC1.62@916.3,422.28 CC1.62@916.3,465.59 CC1.62@959.61,422.28 CC1.62@959.61,465.59 CC1.63@798.19,422.28 CC1.63@798.19,465.59 CC1.63@841.5,422.28 CC1.63@841.5,465.59 FID1.1 FID2.1 FID3.1 H1. H2. H3. H4. J3.7 J3.8 J4.7 J4.9 J4.MH1 J4.MH2 J4.MH3 J14.3 J14.4 J14.5 J14.MH1 J14.MH2 J14.MH3 LBL1.0 P2.17 SH-J5-1.0 SH-J5-2.0 SH-J5-3.0 SH-J5-4.0 SH-J5-5.0 SH-J7.0 SH-J8.0 SH-J9.0 SH-J10.0 SH-J11.0 SH-J12.0 SH-J13.0 SH-J16.0 SH-J18.0 SH-J21.0 SH-J23.0 SH-J24.0 SH-J25.0 U1.2 U1.5 U1.6 U1.11 U1.12 U1.13 U1.14 U1.15 U1.18 U1.19 U1.20 U1.21 U1.22 U1.23 U1.24 U1.25 U1.27 U1.29 U1.30 U1.31 U1.32 U1.41 U1.42 U1.43 U1.44 U1.45 U1.46 U1.49 U1.50 U1.53 U1.54 U1.56 U1.57 U1.65 U1.67 U1.71 U1.72 U1.73 U1.74 U1.75 U1.76 U1.77 U1.78 U1.81 U1.82 U1.83 U1.84 U1.85 U1.86 U1.91 U1.92 U1.102 U1.103 U1.104 U1.105 U1.106 U1.107 U1.108 U1.109 U1.110 U1.111 U1.112 U1.116 U1.117 U1.118 U1.119 U1.120 U1.121 U1.123 U1.124 U1.125 U1.126 U1.127 U1.128 U2.3 U4.3@292.91,3815.67 U4.4 U4.5 U4.6 U4.7 U4.8@292.91,3782.8 U6.9@1562.11,3809.21 U6.9@1562.11,3844.64 U8.4 U8.6 U8.10 U11.3 U11.7@1050.67,1422.6 U11.7@1086.11,1422.6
